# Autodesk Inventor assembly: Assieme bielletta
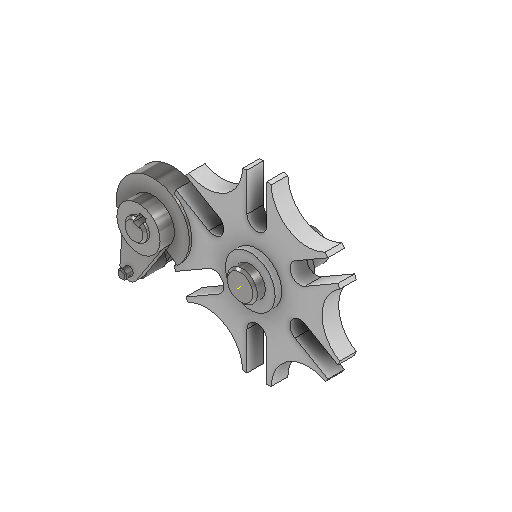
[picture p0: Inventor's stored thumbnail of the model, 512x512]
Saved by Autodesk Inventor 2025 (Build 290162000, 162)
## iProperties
Created: 2025-10
Part Number: Assieme bielletta
Document SubType Name: Assembly
Designer: 18619647
Author: 18619647
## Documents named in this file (9)
- C:\Users\Ryzen5700u\Desktop\trasm. croce di malta\Assieme bielletta.iam
- C:\Users\Ryzen5700u\Desktop\trasm. croce di malta\bielletta.ipt
- C:\Users\Ryzen5700u\Desktop\trasm. croce di malta\perno.ipt
- C:\Users\Ryzen5700u\Desktop\trasm. croce di malta\nottolino.ipt
- C:\Users\Ryzen5700u\Desktop\trasm. croce di malta\bronzina.ipt
- C:\Users\Ryzen5700u\Desktop\trasm. croce di malta\anello.ipt
- C:\Users\Ryzen5700u\Desktop\trasm. croce di malta\perno2.ipt
- C:\Users\Ryzen5700u\Desktop\trasm. croce di malta\croce di malta.ipt
- C:\Users\Ryzen5700u\Desktop\trasm. croce di malta\perno3.ipt
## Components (8 placed, 8 different names)
1. bielletta:1 — Coincidente:3, Coincidente:4, Coincidente:7, Coincidente:8, Coincidente:9, Coincidente:10, Allineato:1, Allineato:3, Rigido:2
2. perno:1 — Coincidente:1, Angolo:1, Coincidente:2, Coincidente:3, Coincidente:9
3. nottolino:1 — Coincidente:1, Angolo:1, Coincidente:2, Coincidente:4
4. bronzina:1 — Coincidente:5, Coincidente:6
5. anello:1 — Coincidente:5, Coincidente:6, Coincidente:7, Coincidente:8
6. perno2:1 — Coincidente:13, Allineato:3, Allineato:4
7. croce di malta:1 — Coincidente:14, Allineato:4
8. perno3:1 — Rigido:2
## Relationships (17: Mate 12, Flush 3, Angle 1, WeldJoint 1)
- Coincidente:1 [Mate]: perno:1 ↔ nottolino:1
- Angolo:1 [Angle]: perno:1 ↔ nottolino:1
- Coincidente:2 [Mate]: perno:1 ↔ nottolino:1
- Coincidente:3 [Mate]: bielletta:1 ↔ perno:1
- Coincidente:4 [Mate]: bielletta:1 ↔ nottolino:1
- Coincidente:5 [Mate]: bronzina:1 ↔ anello:1
- Coincidente:6 [Mate]: bronzina:1 ↔ anello:1
- Coincidente:7 [Mate]: bielletta:1 ↔ anello:1
- Coincidente:8 [Mate]: bielletta:1 ↔ anello:1
- Coincidente:9 [Mate]: bielletta:1 ↔ perno:1
- Coincidente:10 [Mate]: bielletta:1
- Allineato:1 [Flush]: bielletta:1
- Coincidente:13 [Mate]: perno2:1
- Allineato:3 [Flush]: bielletta:1 ↔ perno2:1
- Coincidente:14 [Mate]: croce di malta:1
- Allineato:4 [Flush]: perno2:1 ↔ croce di malta:1
- Rigido:2 [WeldJoint]: bielletta:1 ↔ perno3:1
